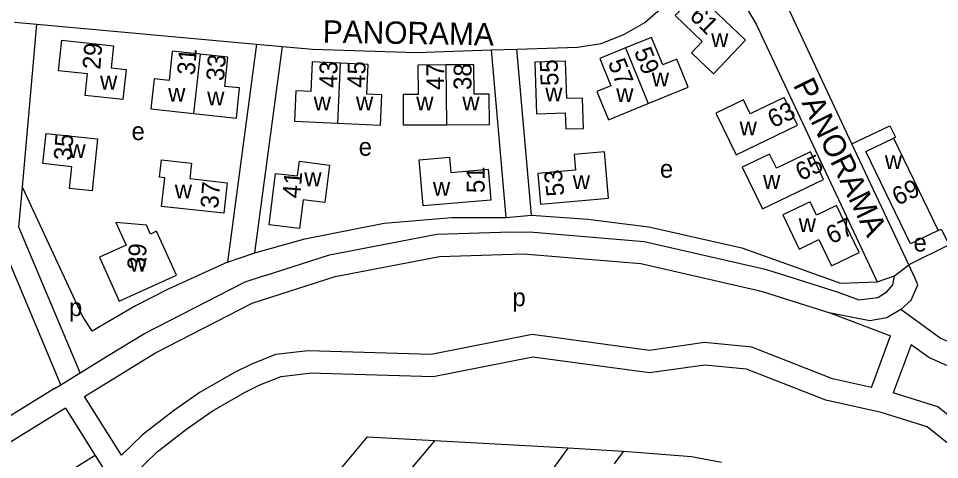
# Model space of a CAD drawing. Extents: x 159441 to 162086, y 388175 to 389787.
# Drawn here: x 161222.1 to 161428.2, y 389484.9 to 389583.7 of the extents above; entities that cross this region are included whole.
import ezdxf

# ---------------------------------------------------------------- set-up
doc = ezdxf.new("R2010")
doc.units = 0
for name, color, linetype in [('BLT_Basislijn', 7, 'Continuous'), ('BLT_Bebouwing', 7, 'Continuous'), ('BLT_Centroide', 7, 'Continuous'), ('BLT_Huisnummer', 7, 'Continuous'), ('BLT_Huisnummer_ tussenligend', 7, 'Continuous'), ('BLT_Onderverdeling_panden', 7, 'Continuous'), ('BLT_Straatnaam', 7, 'Continuous')]:
    doc.layers.add(name, color=color, linetype=linetype)

msp = doc.modelspace()

# ---------------------------------------------------------------- linework, layer by layer
at = {"layer": 'BLT_Basislijn'}
for p, q in [((161221.26, 389582.82), (161226.24, 389582.37)), ((161223.01, 389545.86), (161226.24, 389582.37)), ((161226.24, 389582.37), (161275.37, 389577.89)), ((161275.37, 389577.89), (161268.87, 389529.08)), ((161275.37, 389577.89), (161281.18, 389577.37)), ((161274.97, 389531.19), (161281.18, 389577.37)), ((161327.84, 389576.61), (161333.57, 389576.8)), ((161327.84, 389576.61), (161331.14, 389539.08)), ((161336.85, 389539.59), (161333.57, 389576.8)), ((161421.26, 389528.53), (161408.57, 389555.6)), ((161331.14, 389539.08), (161336.85, 389539.59)), ((161231.59, 389501.64), (161217.14, 389536.14)), ((161332.36, 389535.9), (161337.36, 389535.82)), ((161268.87, 389529.08), (161274.97, 389531.19)), ((161418.12, 389526.05), (161421.26, 389528.53)), ((161422.72, 389525.42), (161421.26, 389528.53)), ((161277.3, 389526.08), (161272.53, 389524.56)), ((161414.23, 389524.72), (161418.12, 389526.05)), ((161389.43, 389522.23), (161403.87, 389517.65)), ((161403.87, 389517.65), (161417.22, 389512.64)), ((161412.93, 389501.04), (161417.22, 389512.64)), ((161421.81, 389510.63), (161417.81, 389499.83)), ((161235.9, 389504.3), (161242.21, 389508.19)), ((161231.59, 389501.64), (161234.58, 389503.49)), ((161234.58, 389503.49), (161235.9, 389504.3)), ((161230.2, 389500.79), (161231.59, 389501.64)), ((161230.2, 389500.79), (161187.73, 389474.61)), ((161232.61, 389496.4), (161198.74, 389475.53)), ((161232.61, 389496.4), (161239.31, 389485.81)), ((161315.16, 389489.14), (161271.95, 389437.78)), ((161300.15, 389489.98), (161285.19, 389472.2)), ((161315.16, 389489.14), (161300.17, 389489.96)), ((161345.1, 389487.49), (161315.16, 389489.14)), ((161336.38, 389475.59), (161345.1, 389487.49)), ((161357.39, 389486.75), (161345.1, 389487.49)), ((161239.31, 389485.81), (161241.31, 389482.65))]:
    msp.add_line(p, q, dxfattribs=at)
for points in [[(161371.1, 389591.72), (161372.38, 389592.11), (161374.13, 389591.92), (161379.47, 389589.74), (161381.69, 389588.35), (161384.94, 389586), (161387.17, 389582.38), (161414.23, 389524.72)], [(161333.57, 389576.8), (161347.16, 389577.24), (161352.47, 389578.06), (161357.57, 389580.03), (161362.21, 389582.76), (161366.3, 389586.29), (161369.74, 389590.48), (161371.1, 389591.72)], [(161408.57, 389555.6), (161393.83, 389587.01), (161392.93, 389587.94)], [(161281.18, 389577.37), (161287.91, 389576.75), (161311.08, 389576.06), (161327.84, 389576.61)], [(161408.57, 389555.6), (161417.01, 389559.63), (161418.29, 389557.05), (161417.88, 389556.85)], [(161235.9, 389504.3), (161222.23, 389536.93), (161223.01, 389545.86)], [(161268.87, 389529.08), (161255.63, 389523.03), (161248.33, 389519.33), (161238.64, 389513.69), (161236.4, 389517.14), (161223.01, 389545.86)], [(161274.97, 389531.19), (161286.18, 389534.29), (161303.95, 389537.82), (161319.03, 389539.1), (161331.14, 389539.08)], [(161336.85, 389539.59), (161349.51, 389538.76), (161363.12, 389537), (161383.9, 389532.34), (161406.03, 389524.38), (161414.23, 389524.72)], [(161427.86, 389536.18), (161428.54, 389536.51), (161430.3, 389532.99), (161421.26, 389528.53)], [(161277.3, 389526.08), (161291.73, 389530.71), (161315.74, 389535.38), (161332.36, 389535.9)], [(161337.36, 389535.82), (161362.12, 389533.75), (161388.87, 389527.58), (161390.87, 389527.02)], [(161236.87, 389499.02), (161252.75, 389508.81), (161274.42, 389519.91), (161292.97, 389525.86), (161316.3, 389530.39), (161335.09, 389530.99), (161361.35, 389528.8), (161387.63, 389522.73), (161389.43, 389522.23)], [(161390.87, 389527.02), (161405.51, 389522.37), (161410.08, 389520.66)], [(161410.08, 389520.66), (161414.34, 389521.16), (161416.4, 389522.45), (161417.74, 389524), (161418.12, 389526.05)], [(161242.21, 389508.19), (161250.3, 389513.17), (161272.53, 389524.56)], [(161419.52, 389518.47), (161421.79, 389520.61), (161423.29, 389524.03), (161422.72, 389525.42)], [(161419.52, 389518.47), (161416.34, 389516.67), (161412.54, 389515.98), (161403.87, 389517.65)], [(161530.5, 389443.58), (161522.03, 389452.09), (161510.21, 389461.22), (161498.99, 389468.19), (161489.49, 389475.11), (161481.93, 389481.84), (161474.86, 389488.78), (161466.99, 389495.13), (161456.52, 389501.73), (161448.47, 389505.52), (161438.87, 389508.66), (161432.92, 389510.04), (161428.28, 389512.12), (161419.52, 389518.47)], [(161412.93, 389501.04), (161404.2, 389502.98), (161386.15, 389510.05), (161375.57, 389511.11), (161363.27, 389509.36), (161337.06, 389512.91), (161314.45, 389508.47), (161286.91, 389509.25)], [(161537.21, 389418.33), (161537.56, 389418.92), (161538.1, 389420.8), (161538.12, 389422.8), (161537.68, 389424.86), (161536.85, 389426.77), (161526.71, 389440.3), (161518.71, 389448.33), (161507.35, 389457.11), (161496.2, 389464.04), (161486.35, 389471.21), (161478.52, 389478.19), (161471.53, 389485.04), (161464.07, 389491.06), (161454.11, 389497.34), (161446.62, 389500.86), (161437.52, 389503.84), (161431.31, 389505.28), (161425.76, 389507.77), (161421.81, 389510.63)], [(161286.91, 389509.25), (161279.65, 389508.4), (161274.08, 389506.21), (161270.45, 389504.38), (161262.76, 389500), (161256.8, 389495.85), (161249.86, 389490.43), (161245.19, 389485.87), (161236.87, 389499.02)], [(161477.78, 389450.24), (161425.41, 389492.21), (161415.13, 389495.43), (161402.74, 389498.19), (161384.97, 389505.14), (161375.67, 389506.07), (161363.28, 389504.32), (161337.21, 389507.84), (161314.86, 389503.46), (161287.13, 389504.24)], [(161245.12, 389478.83), (161253.15, 389486.65), (161259.77, 389491.82), (161265.43, 389495.77), (161272.82, 389499.97), (161276.13, 389501.64), (161280.88, 389503.51), (161287.13, 389504.24)], [(161537.21, 389418.33), (161529.36, 389424.91), (161522.71, 389428.48), (161513.29, 389434.38), (161499.5, 389448.87), (161492.04, 389451.92), (161480.04, 389454.84), (161427.81, 389496.7), (161417.81, 389499.83)], [(161239.31, 389485.81), (161226.5, 389477.94), (161230.54, 389471.36), (161238.64, 389467.9), (161246.28, 389476.97), (161245.12, 389478.83)], [(161357.39, 389486.75), (161355.35, 389483.98)], [(161361.32, 389486.43), (161357.39, 389486.75)], [(161379.36, 389484.27), (161372.66, 389485.51), (161361.32, 389486.43)]]:
    msp.add_lwpolyline(points, dxfattribs=at)
at = {"layer": 'BLT_Bebouwing'}
msp.add_line((161417.88, 389556.85), (161427.86, 389536.18), dxfattribs=at)
for points in [[(161373.82, 389589.3), (161369.03, 389584.32), (161375.08, 389578.49), (161372.65, 389575.97), (161377.56, 389571.27), (161384.74, 389578.77)], [(161243.37, 389577.52), (161242.84, 389572.58), (161246.19, 389572.22), (161245.46, 389565.48), (161237.05, 389566.39), (161237.57, 389571.22), (161231.1, 389571.92), (161231.84, 389578.76)], [(161344.51, 389574.11), (161337.61, 389573.87), (161338, 389562.32), (161344.42, 389562.52), (161344.53, 389558.92), (161348.51, 389559.05), (161348.29, 389565.82), (161344.78, 389565.71)], [(161393.37, 389565.94), (161385.81, 389562.3), (161384.29, 389565.44), (161378.15, 389562.48), (161382.67, 389553.14), (161396.36, 389559.74)], [(161238.57, 389545.06), (161233.51, 389545.6), (161234.04, 389550.47), (161227.57, 389551.16), (161228.3, 389557.93), (161239.82, 389556.69)], [(161338.33, 389548.96), (161338.93, 389542.09), (161354.11, 389543.41), (161353.19, 389553.8), (161346.4, 389553.2), (161346.7, 389549.69)], [(161399.27, 389553.76), (161391.69, 389550.11), (161390.15, 389553.3), (161384.03, 389550.35), (161388.54, 389541), (161402.23, 389547.61)], [(161260.46, 389547.8), (161268.82, 389546.86), (161268.05, 389540.05), (161254.15, 389541.59), (161254.86, 389547.97), (161253.67, 389548.1), (161254.1, 389552.03), (161260.85, 389551.29)], [(161291.71, 389550.84), (161290.64, 389542.45), (161285.78, 389543.07), (161284.98, 389536.62), (161278.18, 389537.48), (161279.63, 389548.97), (161284.56, 389548.45), (161284.98, 389551.7)], [(161318.85, 389549.15), (161327.21, 389549.89), (161327.81, 389543), (161312.68, 389541.68), (161311.78, 389552.02), (161318.54, 389552.62)], [(161405.14, 389541.75), (161400.67, 389539.6), (161399.21, 389542.62), (161393.08, 389539.67), (161396.75, 389532.04), (161401.16, 389534.16), (161403.98, 389528.31), (161410.19, 389531.3)], [(161243.92, 389538.01), (161246.2, 389532.93), (161240.23, 389530.24), (161244.66, 389520.39), (161257.48, 389526.17), (161253.03, 389536.02), (161251.64, 389535.39), (161250.75, 389537.35)]]:
    msp.add_lwpolyline(points, close=True, dxfattribs=at)
for points in [[(161363, 389564.63), (161371.91, 389568.27), (161369.36, 389574.56), (161366.23, 389573.3), (161363.75, 389579.41), (161357.93, 389577.04)], [(161262.73, 389575.67), (161256.5, 389576.34), (161255.8, 389569.78), (161252.45, 389570.14), (161251.73, 389563.42), (161261.29, 389562.36)], [(161261.29, 389562.36), (161270.86, 389561.3), (161271.59, 389568.08), (161268.26, 389568.44), (161268.96, 389575), (161262.73, 389575.67)], [(161357.93, 389577.04), (161352.14, 389574.67), (161354.63, 389568.56), (161351.51, 389567.29), (161354.09, 389560.99), (161363, 389564.63)], [(161294.11, 389573.61), (161287.85, 389573.91), (161287.55, 389567.29), (161284.19, 389567.46), (161283.89, 389560.65), (161293.48, 389560.21)], [(161293.48, 389560.21), (161303.12, 389559.77), (161303.43, 389566.56), (161300.06, 389566.71), (161300.37, 389573.32), (161294.11, 389573.61)], [(161317.75, 389573.26), (161311.49, 389573.21), (161311.53, 389566.63), (161308.18, 389566.6), (161308.21, 389559.8), (161317.84, 389559.85)], [(161317.84, 389559.85), (161327.45, 389559.9), (161327.41, 389566.71), (161324.05, 389566.69), (161324.01, 389573.3), (161317.75, 389573.26)], [(161427.86, 389536.18), (161421.64, 389533.18), (161411.66, 389553.85), (161417.88, 389556.85)]]:
    msp.add_lwpolyline(points, dxfattribs=at)
at = {"layer": 'BLT_Onderverdeling_panden'}
for p, q in [((161262.73, 389575.67), (161261.29, 389562.36)), ((161357.93, 389577.04), (161363, 389564.63)), ((161294.11, 389573.61), (161293.48, 389560.21)), ((161317.75, 389573.26), (161317.84, 389559.85))]:
    msp.add_line(p, q, dxfattribs=at)

# ---------------------------------------------------------------- texts
at = {"layer": 'BLT_Centroide'}
for s, p in [('w', (161377.07, 389577.26)), ('w', (161363.79, 389568.45)), ('w', (161240.37, 389567.74)), ('w', (161255.61, 389565.02)), ('w', (161264.33, 389564.17)), ('w', (161339.95, 389565.11)), ('w', (161355.83, 389564.94)), ('w', (161288.16, 389563.05)), ('w', (161297.62, 389563.05)), ('w', (161311.1, 389563.05)), ('w', (161321.41, 389563.05)), ('e', (161247.41, 389556.43)), ('w', (161383.44, 389557.48)), ('w', (161233.29, 389552.43)), ('e', (161298.23, 389552.92)), ('w', (161415.92, 389549.96)), ('e', (161365.61, 389548.01)), ('w', (161286.06, 389546.1)), ('w', (161314.84, 389543.95)), ('w', (161346.11, 389545.44)), ('w', (161388.69, 389545.5)), ('w', (161257.08, 389543.36)), ('w', (161396.66, 389535.83)), ('e', (161422.33, 389531.49)), ('w', (161246.96, 389526.98)), ('p', (161332.62, 389519.24)), ('p', (161233.42, 389517.02))]:
    msp.add_text(s, height=4, dxfattribs=at).set_placement(p)
at = {"layer": 'BLT_Huisnummer'}
for s, rotation, p in [('61', 315.4703, (161371.98, 389583.93)), ('29', 85.4703, (161240.41, 389572.11)), ('59', 291.4703, (161359.75, 389576.27)), ('33', 85.4703, (161268.07, 389569.55)), ('43', 89.4703, (161293.43, 389568.11)), ('55', 92.4703, (161342.95, 389568.62)), ('47', 89.4703, (161317.32, 389567.62)), ('38', 89.4703, (161323.44, 389567.63)), ('63', 25.4703, (161390.92, 389559.04)), ('35', 85.4703, (161233.96, 389551.74)), ('41', 85.4703, (161285.14, 389543.29)), ('51', 90.4703, (161326.41, 389544.58)), ('53', 96.4703, (161344.28, 389544.07)), ('37', 85.4703, (161266.78, 389541.01)), ('69', 25.4703, (161418.75, 389541.69)), ('67', 25.4703, (161403.97, 389533.05)), ('39', 85.4703, (161250.39, 389527.21))]:
    msp.add_text(s, height=4, rotation=rotation, dxfattribs=at).set_placement(p)
at = {"layer": 'BLT_Huisnummer_ tussenligend'}
for s, rotation, p in [('31', 85.4703, (161261.56, 389570.85)), ('45', 89.4703, (161299.7, 389568.11)), ('57', 291.4703, (161353.9, 389573.76)), ('65', 25.4703, (161397.13, 389547.21))]:
    msp.add_text(s, height=4, rotation=rotation, dxfattribs=at).set_placement(p)
at = {"layer": 'BLT_Straatnaam'}
for rotation, p in [(358.9998, (161290.16, 389578.25)), (295.9998, (161395.29, 389568.78))]:
    msp.add_text('PANORAMA', height=5, rotation=rotation, dxfattribs=at).set_placement(p)

doc.saveas('drawing.dxf')
